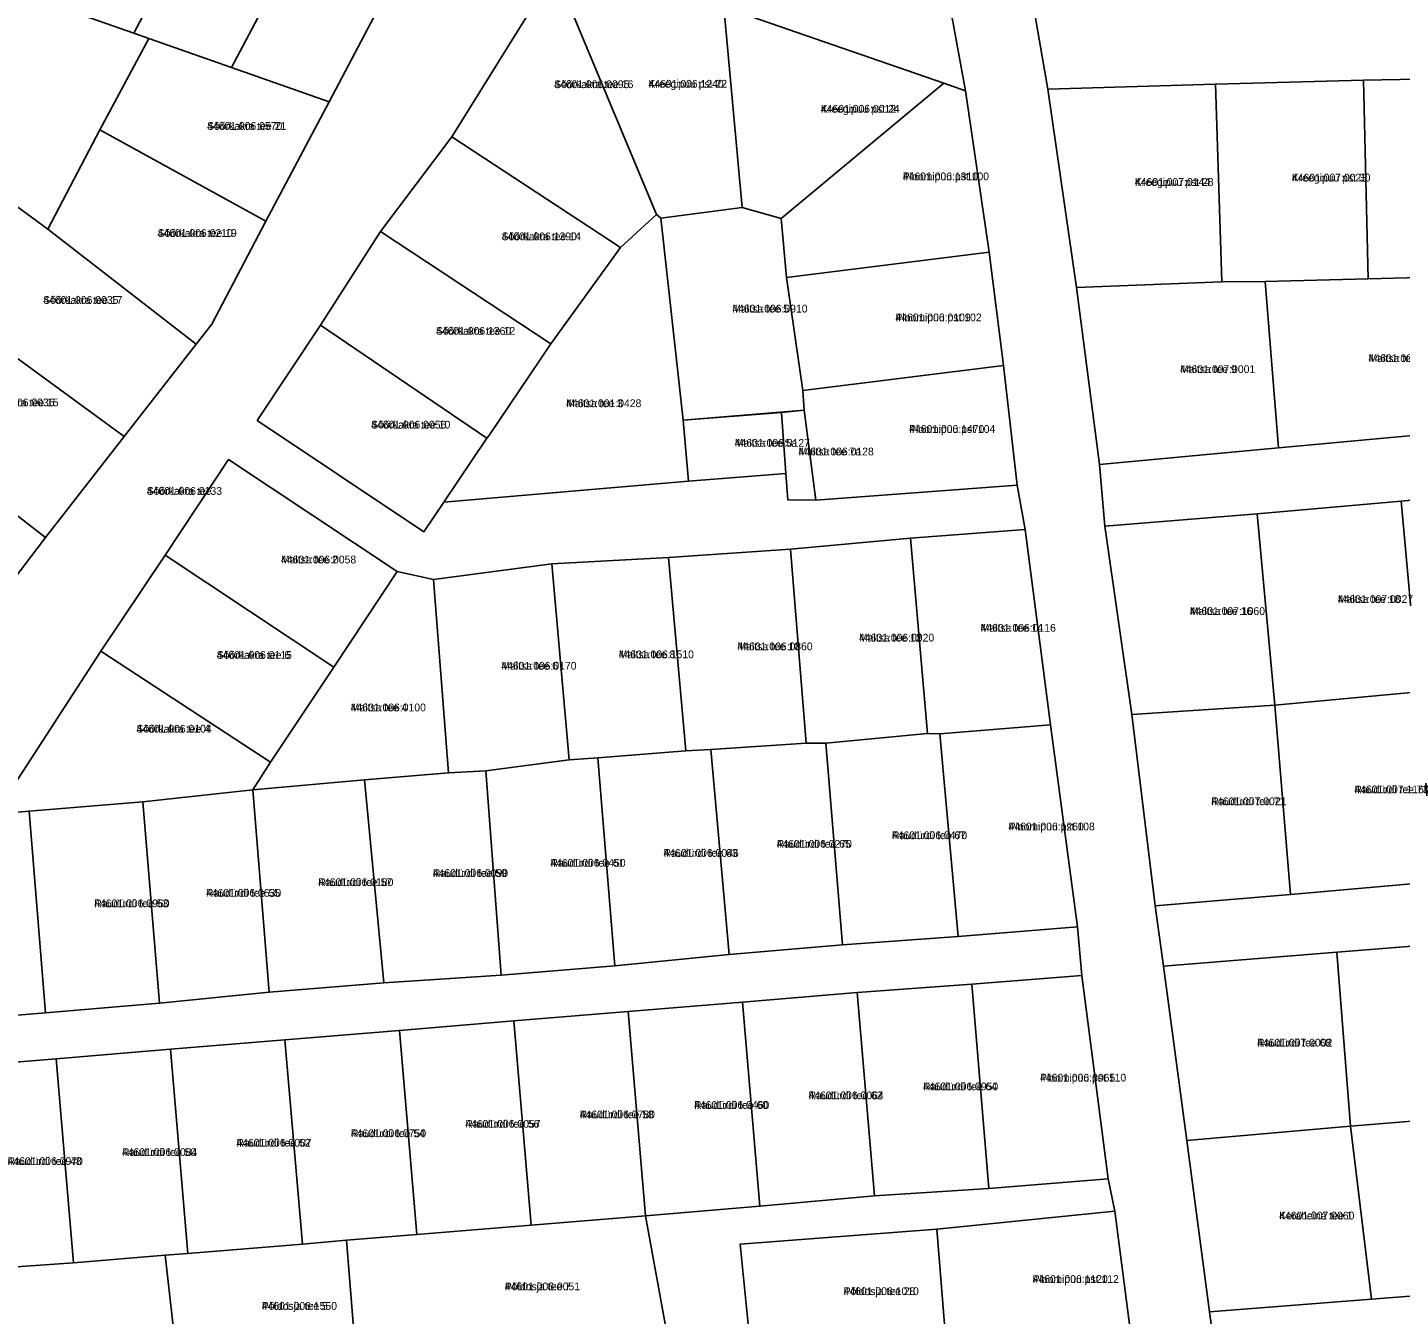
# Model space of a CAD drawing. Extents: x 551843 to 558501, y 6589003 to 6595718.
# Drawn here: x 553854.7 to 554119.5, y 6592803.2 to 6593051.3 of the extents above; entities that cross this region are included whole.
import ezdxf

# ---------------------------------------------------------------- set-up
doc = ezdxf.new("R2010")
doc.units = 0
for name, color, linetype in [('L_AADRESS', 7, 'Continuous'), ('PIIR', 7, 'Continuous'), ('TUNNUS', 7, 'Continuous')]:
    doc.layers.add(name, color=color, linetype=linetype)

msp = doc.modelspace()

# ---------------------------------------------------------------- linework, layer by layer
at = {"layer": 'PIIR'}
for points in [[(553854.75, 6593057.46), (553877.3, 6593094.1), (553895.01, 6593087.85), (553875.19, 6593050.25)], [(553913.88, 6593081.12), (553894.03, 6593043.62), (553878.12, 6593049.22), (553875.19, 6593050.25), (553895.01, 6593087.85)], [(553913.88, 6593081.12), (553932.68, 6593074.58), (553912.87, 6593037.01), (553894.03, 6593043.62)], [(553988.97, 6593055.28), (553992.55, 6593016.61), (553976.81, 6593014.6), (553976, 6593015.3), (553960.37, 6593052.69), (553956.34, 6593062.1), (553958.82, 6593066)], [(553956.34, 6593062.1), (553960.37, 6593052.69), (553976, 6593015.3), (553969.07, 6593008.89), (553936.54, 6593030.26)], [(554031.39, 6593040.61), (554000.05, 6593014.53), (553992.55, 6593016.61), (553988.97, 6593055.28)], [(553868.67, 6593031.61), (553878.12, 6593049.22), (553894.03, 6593043.62), (553912.87, 6593037.01), (553900.66, 6593013.99)], [(554035.59, 6593039.14), (554040.18, 6593008.01), (554001.1, 6593003.15), (554000.05, 6593014.53), (554031.39, 6593040.61)], [(554051.46, 6593039.45), (554083.78, 6593040.41), (554085.03, 6593002.29), (554056.98, 6593001.21)], [(554112.35, 6593041.16), (554113.25, 6593002.9), (554093.35, 6593002.34), (554085.03, 6593002.29), (554083.78, 6593040.41)], [(554130.68, 6593003.34), (554113.25, 6593002.9), (554112.35, 6593041.16), (554140.76, 6593041.72), (554142.47, 6593003.75)], [(553900.66, 6593013.99), (553890.26, 6592994.15), (553887.21, 6592990.29), (553858.61, 6593012.42), (553868.67, 6593031.61)], [(553922.8, 6593012), (553936.54, 6593030.26), (553969.07, 6593008.89), (553955.65, 6592990.36)], [(553858.61, 6593012.42), (553887.21, 6592990.29), (553873.32, 6592972.49), (553844.04, 6592993.87), (553830.71, 6593003.6), (553843.32, 6593023.62)], [(553992.55, 6593016.61), (554000.05, 6593014.53), (554001.1, 6593003.15), (554004.23, 6592981.35), (554004.45, 6592977.53), (553981.15, 6592975.6), (553976.81, 6593014.6)], [(553982.18, 6592963.89), (553934.98, 6592959.8), (553943.3, 6592972.17), (553943.7, 6592972.6), (553955.65, 6592990.36), (553969.07, 6593008.89), (553976, 6593015.3), (553976.81, 6593014.6), (553981.15, 6592975.6)], [(553955.65, 6592990.36), (553943.7, 6592972.6), (553943.3, 6592972.17), (553911.22, 6592993.92), (553922.8, 6593012)], [(554004.23, 6592981.35), (554001.1, 6593003.15), (554040.18, 6593008.01), (554042.93, 6592986.15)], [(553829.51, 6592975.16), (553814.07, 6592987.07), (553830.71, 6593003.6), (553844.04, 6592993.87), (553873.32, 6592972.49), (553858.19, 6592952.97)], [(554093.35, 6593002.34), (554113.25, 6593002.9), (554130.68, 6593003.34), (554133.06, 6592973.7), (554095.98, 6592970.3)], [(554056.98, 6593001.21), (554085.03, 6593002.29), (554093.35, 6593002.34), (554095.98, 6592970.3), (554061.41, 6592967.05)], [(553943.3, 6592972.17), (553934.98, 6592959.8), (553931.12, 6592954.1), (553899.02, 6592975.57), (553911.22, 6592993.92)], [(553815.74, 6592957.1), (553800.68, 6592974.68), (553814.07, 6592987.07), (553829.51, 6592975.16), (553858.19, 6592952.97), (553843.76, 6592934.1), (553842.76, 6592932.9)], [(554042.93, 6592986.15), (554045.57, 6592963.12), (554006.7, 6592960.2), (554004.45, 6592977.53), (554004.23, 6592981.35)], [(554061.41, 6592967.05), (554095.98, 6592970.3), (554133.06, 6592973.7), (554173.07, 6592976.86), (554211.72, 6592979.66), (554260.66, 6592983.71), (554258, 6592971.5), (554230.39, 6592969.26), (554202.78, 6592967.02), (554175.41, 6592964.8), (554147.41, 6592962.61), (554119.61, 6592959.98), (554091.85, 6592957.57), (554062.46, 6592955.16)], [(553981.15, 6592975.6), (554000.09, 6592977.1), (554000.96, 6592965.32), (553982.18, 6592963.89)], [(554000.09, 6592977.1), (554004.45, 6592977.53), (554006.7, 6592960.2), (554001.34, 6592960.25), (554000.96, 6592965.32)], [(553893.49, 6592968.01), (553925.97, 6592946.42), (553913.75, 6592927.99), (553881.23, 6592949.57)], [(554119.61, 6592959.98), (554122.96, 6592923.26), (554095.24, 6592920.69), (554091.85, 6592957.57)], [(554095.24, 6592920.69), (554067.69, 6592918.9), (554062.46, 6592955.16), (554091.85, 6592957.57)], [(554025.01, 6592952.86), (554028.25, 6592915.18), (554008.66, 6592913.34), (554004.87, 6592913.34), (554001.84, 6592950.73)], [(554025.01, 6592952.86), (554047.09, 6592954.52), (554052.01, 6592916.88), (554030.61, 6592915.15), (554028.25, 6592915.18)], [(554001.84, 6592950.73), (554004.87, 6592913.34), (553986.5, 6592912.15), (553981.64, 6592911.84), (553978.34, 6592949.14)], [(553868.82, 6592931.09), (553881.23, 6592949.57), (553913.75, 6592927.99), (553901.59, 6592909.65)], [(553935.92, 6592907.61), (553932.97, 6592944.93), (553955.79, 6592947.91), (553959.19, 6592910.12), (553943.09, 6592908.01)], [(553978.34, 6592949.14), (553981.64, 6592911.84), (553964.72, 6592910.52), (553959.19, 6592910.12), (553955.79, 6592947.91)], [(553919.7, 6592906.28), (553898.13, 6592904.33), (553901.59, 6592909.65), (553913.75, 6592927.99), (553925.97, 6592946.42), (553932.97, 6592944.93), (553935.92, 6592907.61)], [(553848.43, 6592899.68), (553868.82, 6592931.09), (553901.59, 6592909.65), (553898.13, 6592904.33), (553876.96, 6592902.05), (553855.01, 6592900.23)], [(554122.96, 6592923.26), (554125.93, 6592886.61), (554098.28, 6592884.15), (554095.24, 6592920.69)], [(554095.24, 6592920.69), (554098.28, 6592884.15), (554072.19, 6592882.01), (554067.69, 6592918.9)], [(554052.01, 6592916.88), (554057.19, 6592877.91), (554034.16, 6592876.04), (554030.61, 6592915.15)], [(553986.5, 6592912.15), (554004.87, 6592913.34), (554008.66, 6592913.34), (554011.85, 6592874.48), (553989.99, 6592872.61)], [(554008.66, 6592913.34), (554028.25, 6592915.18), (554030.61, 6592915.15), (554034.16, 6592876.04), (554011.85, 6592874.48)], [(553943.09, 6592908.01), (553959.19, 6592910.12), (553964.72, 6592910.52), (553967.98, 6592870.43), (553946.03, 6592868.61)], [(553981.64, 6592911.84), (553986.5, 6592912.15), (553989.99, 6592872.61), (553967.98, 6592870.43), (553964.72, 6592910.52)], [(553919.7, 6592906.28), (553935.92, 6592907.61), (553943.09, 6592908.01), (553946.03, 6592868.61), (553923.4, 6592867.13)], [(553898.13, 6592904.33), (553919.7, 6592906.28), (553923.4, 6592867.13), (553901.3, 6592865.35)], [(553876.96, 6592902.05), (553898.13, 6592904.33), (553901.3, 6592865.35), (553880.15, 6592863.19)], [(553848.43, 6592899.68), (553855.01, 6592900.22), (553858.2, 6592861.37), (553820.9, 6592858.29)], [(553855.01, 6592900.22), (553876.96, 6592902.05), (553880.15, 6592863.19), (553858.2, 6592861.37)], [(554072.19, 6592882.01), (554098.28, 6592884.15), (554125.93, 6592886.61), (554153.39, 6592888.86), (554181.16, 6592891.18), (554208.49, 6592893.43), (554236.15, 6592895.73), (554263.08, 6592898.06), (554264.42, 6592885.66), (554232.89, 6592883.22), (554201.27, 6592880.71), (554170.05, 6592878.08), (554138.71, 6592875.53), (554107.19, 6592873.02), (554073.79, 6592870.33)], [(554107.19, 6592873.02), (554109.85, 6592839.49), (554078.3, 6592836.73), (554073.79, 6592870.33)], [(554138.71, 6592875.53), (554141.34, 6592842.08), (554109.85, 6592839.49), (554107.19, 6592873.02)], [(554058, 6592868.57), (554063.09, 6592829.35), (554040.12, 6592827.49), (554036.82, 6592866.85)], [(554014.68, 6592865.24), (554018.03, 6592826.05), (553995.96, 6592824.06), (553992.61, 6592863.42)], [(554036.82, 6592866.85), (554040.12, 6592827.49), (554018.03, 6592826.05), (554014.68, 6592865.24)], [(553992.61, 6592863.42), (553995.96, 6592824.06), (553973.9, 6592822.24), (553970.55, 6592861.6)], [(553948.49, 6592859.78), (553951.84, 6592820.42), (553929.78, 6592818.61), (553926.43, 6592857.97)], [(553970.55, 6592861.6), (553973.9, 6592822.24), (553951.84, 6592820.42), (553948.49, 6592859.78)], [(553926.43, 6592857.97), (553929.78, 6592818.61), (553916.21, 6592817.49), (553907.71, 6592816.78), (553904.36, 6592856.14)], [(553904.36, 6592856.14), (553907.71, 6592816.78), (553885.65, 6592814.96), (553882.29, 6592854.32)], [(553863.58, 6592813.14), (553847.87, 6592812.08), (553841.52, 6592811.32), (553838.16, 6592850.68), (553860.22, 6592852.5)], [(553860.22, 6592852.5), (553882.29, 6592854.32), (553885.65, 6592814.96), (553881.27, 6592814.65), (553863.58, 6592813.14)], [(554141.34, 6592842.08), (554144.37, 6592808.55), (554113.87, 6592806.14), (554109.85, 6592839.49)], [(554109.85, 6592839.49), (554113.87, 6592806.14), (554082.62, 6592803.68), (554078.3, 6592836.73)], [(554032.02, 6592795.42), (554031.86, 6592797.34), (554030.06, 6592819.61), (554064.38, 6592823.12), (554067.54, 6592798.8)], [(553929.78, 6592818.61), (553951.84, 6592820.42), (553973.9, 6592822.24), (553978.2, 6592798.54), (553952.52, 6592796.34), (553918.18, 6592793.47), (553916.21, 6592817.49)], [(553881.27, 6592814.65), (553885.65, 6592814.96), (553907.71, 6592816.78), (553916.21, 6592817.49), (553918.18, 6592793.47), (553883.98, 6592790.69)], [(553994.39, 6592794.25), (553992.11, 6592816.73), (554030.06, 6592819.61), (554031.86, 6592797.34)], [(554082.62, 6592803.68), (554113.87, 6592806.14), (554144.37, 6592808.55), (554176.22, 6592811.29), (554206.55, 6592813.91), (554238.02, 6592816.61), (554269.06, 6592818.81), (554270.06, 6592806.81), (554243.92, 6592805.23), (554217.53, 6592802.75), (554191.38, 6592800.49), (554165.59, 6592798.47), (554139.85, 6592796.36), (554113.8, 6592794.24), (554084.25, 6592791.8)], [(553863.58, 6592813.14), (553881.27, 6592814.65), (553883.98, 6592790.69), (553849.36, 6592787.64), (553847.87, 6592812.08)]]:
    msp.add_lwpolyline(points, close=True, dxfattribs=at)
for points in [[(553843.76, 6592934.1), (553858.19, 6592952.97), (553873.32, 6592972.49), (553887.21, 6592990.29), (553890.26, 6592994.15), (553900.66, 6593013.99), (553912.87, 6593037.01), (553932.68, 6593074.58)], [(553956.34, 6593062.1), (553936.54, 6593030.26), (553922.8, 6593012), (553911.22, 6592993.92), (553899.02, 6592975.57), (553931.12, 6592954.1), (553934.98, 6592959.8), (553982.18, 6592963.89), (554000.96, 6592965.32), (554001.34, 6592960.25), (554006.7, 6592960.2), (554045.57, 6592963.12), (554047.09, 6592954.52), (554025.01, 6592952.86), (554001.84, 6592950.73), (553978.34, 6592949.14), (553955.79, 6592947.91), (553932.97, 6592944.93), (553925.97, 6592946.42), (553893.49, 6592968.01), (553881.23, 6592949.57), (553868.82, 6592931.09), (553848.43, 6592899.68)], [(554031.74, 6593060.29), (554035.59, 6593039.14), (554031.39, 6593040.61), (553988.97, 6593055.28)], [(554092.36, 6592613.03), (554090.37, 6592621.71), (554085.23, 6592660.49), (554080.2, 6592699.24), (554080.16, 6592708.92), (554077.09, 6592730.31), (554073.9, 6592752.46), (554070.73, 6592775.3), (554067.54, 6592798.8), (554064.38, 6592823.12), (554063.09, 6592829.35), (554058, 6592868.57), (554057.19, 6592877.91), (554052.01, 6592916.88), (554047.09, 6592954.52), (554045.57, 6592963.12), (554042.93, 6592986.15), (554040.18, 6593008.01), (554035.59, 6593039.14), (554031.74, 6593060.29)], [(554047.89, 6593060.25), (554051.46, 6593039.45), (554056.98, 6593001.21), (554061.41, 6592967.05), (554062.46, 6592955.16), (554067.69, 6592918.9), (554072.19, 6592882.01), (554073.79, 6592870.33), (554078.3, 6592836.73), (554082.62, 6592803.68), (554084.25, 6592791.8), (554089.08, 6592751.51), (554093.97, 6592709.01), (554096.53, 6592697.08), (554106.93, 6592625.38), (554107.73, 6592613.69), (554113.47, 6592571.05), (554117.98, 6592534.46), (554119.63, 6592521.81)], [(554393.23, 6593051.33), (554367.77, 6593049.72), (554341.21, 6593048.04), (554314.82, 6593047.08), (554284.88, 6593045.98), (554266.15, 6593044.67), (554266.74, 6593036.15), (554259.82, 6593035.44), (554260.58, 6593028.02), (554254.24, 6593027.69), (554253.32, 6593043.75), (554252.74, 6593044.67), (554225.05, 6593044.16), (554196.68, 6593043.29), (554168.59, 6593042.59), (554140.76, 6593041.72), (554112.35, 6593041.16), (554083.78, 6593040.41), (554051.46, 6593039.45), (554047.89, 6593060.25)], [(553854.75, 6593057.46), (553875.19, 6593050.25), (553878.12, 6593049.22), (553868.67, 6593031.61), (553858.61, 6593012.42), (553843.32, 6593023.62)], [(553820.9, 6592858.29), (553858.2, 6592861.37), (553880.15, 6592863.19), (553901.3, 6592865.35), (553923.4, 6592867.13), (553946.03, 6592868.61), (553967.98, 6592870.43), (553989.99, 6592872.61), (554011.85, 6592874.48), (554034.16, 6592876.04), (554057.19, 6592877.91), (554058, 6592868.57), (554036.82, 6592866.85), (554014.68, 6592865.24), (553992.61, 6592863.42), (553970.55, 6592861.6), (553948.49, 6592859.78), (553926.43, 6592857.97), (553904.36, 6592856.14), (553882.29, 6592854.32), (553860.22, 6592852.5), (553838.16, 6592850.68)], [(553978.2, 6592798.54), (553973.9, 6592822.24), (553995.96, 6592824.06), (554018.03, 6592826.05), (554040.12, 6592827.49), (554063.09, 6592829.35), (554064.38, 6592823.12), (554030.06, 6592819.61), (553992.11, 6592816.73), (553994.39, 6592794.25)]]:
    msp.add_lwpolyline(points, dxfattribs=at)

# ---------------------------------------------------------------- texts
at = {"layer": 'L_AADRESS'}
for s, p in [('Sõõrkakra tee 16', (553956.27, 6593039.64)), ('Kreegipuu pst 22', (553974.45, 6593039.73)), ('Kreegipuu pst 24', (554007.7, 6593034.91)), ('Sõõrkakra tee 21', (553889.34, 6593031.6)), ('Ploomipuu pst 100', (554023.51, 6593021.88)), ('Kreegipuu pst 28', (554068.25, 6593020.8)), ('Kreegipuu pst 30', (554098.52, 6593021.64)), ('Sõõrkakra tee 19', (553879.79, 6593010.95)), ('Sõõrkakra tee 14', (553946.14, 6593010.31)), ('Sõõrkakra tee 17', (553857.74, 6592998.05)), ('Maltsa tee 5', (553990.63, 6592996.38)), ('Ploomipuu pst 102', (554022.09, 6592994.68)), ('Sõõrkakra tee 12', (553933.48, 6592992.09)), ('Maltsa tee 11', (554113.32, 6592986.82)), ('Maltsa tee 9', (554076.96, 6592984.7)), ('Sõõrkakra tee 15', (553845.42, 6592978.29)), ('Maltsa tee 3', (553958.58, 6592978.13)), ('Sõõrkakra tee 10', (553920.97, 6592974.01)), ('Ploomipuu pst 104', (554024.72, 6592973.17)), ('Maltsa tee 5a', (553991.09, 6592970.5)), ('Maltsa tee 7a', (554003.4, 6592968.83)), ('Sõõrkakra tee', (553877.71, 6592961.23)), ('Maltsa tee 2', (553903.59, 6592948)), ('Maltsa tee 18', (554107.41, 6592940.37)), ('Maltsa tee 16', (554078.85, 6592938.06)), ('Maltsa tee 12', (554015.05, 6592932.94)), ('Maltsa tee 14', (554038.51, 6592934.83)), ('Sõõrkakra tee 6', (553891.2, 6592929.61)), ('Maltsa tee 8', (553968.71, 6592929.72)), ('Maltsa tee 10', (553991.61, 6592931.26)), ('Maltsa tee 6', (553946.08, 6592927.52)), ('Maltsa tee 4', (553917.03, 6592919.48)), ('Sõõrkakra tee 4', (553875.72, 6592915.38)), ('Raudürdi tee 73', (554110.59, 6592903.68)), ('Raudürdi tee 71', (554082.98, 6592901.39)), ('Ploomipuu pst 108', (554043.9, 6592896.53)), ('Raudürdi tee 65', (553999.18, 6592893.18)), ('Raudürdi tee 67', (554021.41, 6592894.84)), ('Raudürdi tee 63', (553977.36, 6592891.43)), ('Raudürdi tee 59', (553932.87, 6592887.55)), ('Raudürdi tee 61', (553955.54, 6592889.52)), ('Raudürdi tee 57', (553910.77, 6592885.79)), ('Raudürdi tee 55', (553889.13, 6592883.73)), ('Raudürdi tee 53', (553867.58, 6592881.71)), ('Raudürdi tee 68', (554091.82, 6592854.85)), ('Ploomipuu pst 110', (554049.96, 6592848.1)), ('Raudürdi tee 64', (554027.4, 6592846.41)), ('Raudürdi tee 60', (553983.25, 6592842.83)), ('Raudürdi tee 62', (554005.32, 6592844.69)), ('Raudürdi tee 58', (553961.2, 6592841.01)), ('Raudürdi tee 54', (553917.07, 6592837.38)), ('Raudürdi tee 56', (553939.14, 6592839.2)), ('Raudürdi tee 52', (553895, 6592835.55)), ('Raudürdi tee 48', (553850.87, 6592832.01)), ('Raudürdi tee 50', (553872.93, 6592833.74)), ('Keraheina tee 1', (554096.08, 6592821.51)), ('Põldosja tee 7', (553946.76, 6592807.85)), ('Ploomipuu pst 112', (554048.54, 6592809.27)), ('Põldosja tee 28', (554012.09, 6592806.93)), ('Põldosja tee 5', (553899.89, 6592804.09))]:
    msp.add_text(s, height=1.5, dxfattribs=at).set_placement(p)
at = {"layer": 'TUNNUS'}
for s, p in [('44601:006:0095', (553956.27, 6593039.64)), ('44601:006:1240', (553974.45, 6593039.73)), ('44601:006:0012', (554007.7, 6593034.91)), ('44601:006:0570', (553889.34, 6593031.6)), ('44601:006:1310', (554023.51, 6593021.88)), ('44601:007:0144', (554068.25, 6593020.8)), ('44601:007:0023', (554098.52, 6593021.64)), ('44601:006:0210', (553879.79, 6593010.95)), ('44601:006:1390', (553946.14, 6593010.31)), ('44601:006:0035', (553857.74, 6592998.05)), ('44601:006:0910', (553990.63, 6592996.38)), ('44601:006:0109', (554022.09, 6592994.68)), ('44601:006:1360', (553933.48, 6592992.09)), ('44601:007:1180', (554113.32, 6592986.82)), ('44601:007:0001', (554076.96, 6592984.7)), ('44601:006:0036', (553845.42, 6592978.29)), ('44601:001:0428', (553958.58, 6592978.13)), ('44601:006:0056', (553920.97, 6592974.01)), ('44601:006:1470', (554024.72, 6592973.17)), ('44601:006:0127', (553991.09, 6592970.5)), ('44601:006:0128', (554003.4, 6592968.83)), ('44601:006:0133', (553877.71, 6592961.23)), ('44601:006:0058', (553903.59, 6592948)), ('44601:007:0027', (554107.41, 6592940.37)), ('44601:007:1060', (554078.85, 6592938.06)), ('44601:006:0920', (554015.05, 6592932.94)), ('44601:006:0116', (554038.51, 6592934.83)), ('44601:006:1510', (553968.71, 6592929.72)), ('44601:006:0860', (553991.61, 6592931.26)), ('44601:006:0115', (553891.2, 6592929.61)), ('44601:006:0170', (553946.08, 6592927.52)), ('44601:006:0100', (553917.03, 6592919.48)), ('44601:006:0104', (553875.72, 6592915.38)), ('44601:007:1160', (554110.59, 6592903.68)), ('44601:007:0021', (554082.98, 6592901.39)), ('44601:006:1260', (554043.9, 6592896.53)), ('44601:006:0270', (553999.18, 6592893.18)), ('44601:006:0470', (554021.41, 6592894.84)), ('44601:006:0046', (553977.36, 6592891.43)), ('44601:006:0090', (553932.87, 6592887.55)), ('44601:006:0450', (553955.54, 6592889.52)), ('44601:006:0180', (553910.77, 6592885.79)), ('44601:006:0630', (553889.13, 6592883.73)), ('44601:006:0960', (553867.58, 6592881.71)), ('44601:007:0002', (554091.82, 6592854.85)), ('44601:006:0065', (554049.96, 6592848.1)), ('44601:006:0950', (554027.4, 6592846.41)), ('44601:006:0460', (553983.25, 6592842.83)), ('44601:006:0064', (554005.32, 6592844.69)), ('44601:006:0780', (553961.2, 6592841.01)), ('44601:006:0750', (553917.07, 6592837.38)), ('44601:006:0057', (553939.14, 6592839.2)), ('44601:006:0007', (553895, 6592835.55)), ('44601:006:0970', (553850.87, 6592832.01)), ('44601:006:0084', (553872.93, 6592833.74)), ('44601:007:0060', (554096.08, 6592821.51)), ('44601:006:0051', (553946.76, 6592807.85)), ('44601:006:1120', (554048.54, 6592809.27)), ('44601:006:1010', (554012.09, 6592806.93)), ('44601:006:1550', (553899.89, 6592804.09))]:
    msp.add_text(s, height=1.5, dxfattribs=at).set_placement(p)

doc.saveas('drawing.dxf')
